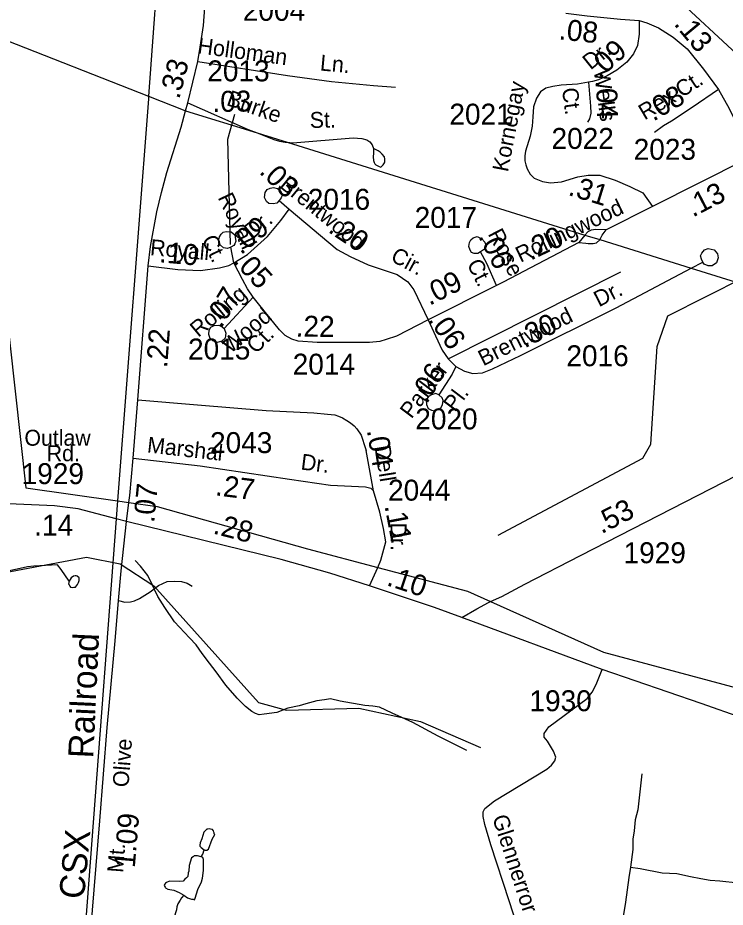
# Model space of a CAD drawing. Extents: x 2206922 to 2357709, y 510027 to 673830.
# Drawn here: x 2287259 to 2291479, y 559014 to 564319 of the extents above; entities that cross this region are included whole.
import ezdxf

# ---------------------------------------------------------------- set-up
doc = ezdxf.new("R2010")
doc.units = 0
for name, color, linetype in [('Exist Boundary Political Urban Extension UEB', 7, 'Continuous'), ('Exist Hydrographic Creek Single Shore', 7, 'Continuous'), ('Exist Hydrographic Misc Water Feature', 7, 'Continuous'), ('Exist Railroad Mainline', 7, 'Continuous'), ('Exist Railroad Mainline Label', 7, 'Continuous'), ('Exist Road Non-System Type 51', 7, 'Continuous'), ('Exist Road Non-System Type 51 Label', 7, 'Continuous'), ('Exist Road Secondary Mileage Hundredths English Label', 7, 'Continuous'), ('Exist Road Secondary Type 51 Attributed', 7, 'Continuous'), ('Exist Road Secondary Type 51 Label', 7, 'Continuous'), ('Exist Road Secondary Type 51 Number Label', 7, 'Continuous'), ('Exist Utilities Electrical Transmission Line', 7, 'Continuous')]:
    doc.layers.add(name, color=color, linetype=linetype)

msp = doc.modelspace()

# ---------------------------------------------------------------- linework, layer by layer
at = {"layer": 'Exist Boundary Political Urban Extension UEB'}
msp.add_line((2287853.8, 561437.5), (2287921.7, 561427.8), dxfattribs=at)
for points in [[(2286979.2, 564267.7), (2287082, 563533.1), (2287306.2, 561515.7), (2287853.8, 561437.5)], [(2287921.7, 561427.8), (2288090.9, 561403.6), (2288987.7, 561151.5), (2289405.5, 561040.9)], [(2289405.5, 561040.9), (2289940.5, 560899.3), (2290079.5, 560836.9)], [(2290079.5, 560836.9), (2290753.2, 560535), (2291902.2, 560226.8), (2292770.9, 559694.4), (2293331.4, 559386.2), (2293609.2, 559370.1)]]:
    msp.add_lwpolyline(points, dxfattribs=at)
at = {"layer": 'Exist Hydrographic Creek Single Shore'}
for points in [[(2291546.8, 564103.5), (2291193.9, 564432), (2290915.9, 564798.4), (2290897.9, 564972.5), (2291069.9, 565297), (2291117.9, 565456.7), (2291099, 565689.9), (2290904, 566130.1), (2290713.9, 566760.3), (2290342, 567423.7), (2290123, 567697), (2289853.9, 567876.3), (2289016.9, 568368.7), (2288882.8, 568427.2), (2288622, 568688.3), (2288246.9, 568777.9), (2288070.8, 568876.5), (2287919.9, 569033.7), (2287807.9, 569373.8)], [(2290125, 561233.1), (2290986.8, 561691.3), (2291035.9, 561775.5), (2291071.9, 562358.5), (2291136.9, 562540.9), (2291593, 562771.1)]]:
    msp.add_lwpolyline(points, dxfattribs=at)
at = {"layer": 'Exist Hydrographic Misc Water Feature'}
for points in [[(2284539.8, 559099.4), (2285578.8, 560206.6), (2285841.9, 560611.3), (2286030.9, 560820.6), (2286146.8, 560903.5), (2286697, 560918.6), (2287668.9, 561102.3), (2287869.9, 561062.2), (2288070.8, 560930.3), (2288694, 560235.6), (2288860.9, 560189.6), (2289293.9, 560200.5), (2289661, 560120.9), (2290019.8, 559966.1)], [(2287496.5, 561055.4), (2287354.6, 561048), (2287316.4, 561043.6), (2287254.9, 561031), (2287159.1, 561010.1), (2287087.6, 560991.3), (2286933.4, 560963.9), (2286831.9, 560941), (2286756, 560922.4), (2286716.4, 560916.2), (2286692.2, 560909.7), (2286656.1, 560907.5), (2286632.6, 560905.4), (2286604.5, 560903.1), (2286584.4, 560904.9), (2286562.4, 560908.6), (2286540.3, 560908.3), (2286534.5, 560909.4), (2286530.4, 560910.2)], [(2287565.3, 560957.9), (2287517, 561027.6), (2287496.5, 561055.4)], [(2289937.8, 559948.8), (2289767, 560033.4), (2289616.1, 560115.7), (2289550, 560145.1), (2289491.8, 560170.6), (2289417.4, 560206.1), (2289377.4, 560213.3), (2289329.4, 560216.9), (2289181.4, 560243.7), (2289123.3, 560257.2), (2289089.1, 560250.7), (2289043.4, 560244.2), (2288977.3, 560227.8), (2288937.4, 560215.5), (2288869.9, 560200.5), (2288804.1, 560176), (2288728, 560165.5), (2288698.5, 560161.1), (2288676.3, 560168.9), (2288654, 560180.8), (2288617.9, 560210.5), (2288567.4, 560259.9), (2288498.9, 560339.2), (2288441.9, 560418.7), (2288401.8, 560470.1), (2288359.1, 560527.7), (2288322.6, 560579.4), (2288282.2, 560620.8), (2288193.6, 560716), (2288136.8, 560801.2), (2288094.2, 560866.9), (2288071.6, 560912.8), (2288063.6, 560930.7), (2288034.7, 560992.6), (2287990.4, 561047.9), (2287959.9, 561081.7)], [(2287565.3, 560957.9), (2287561.7, 560941.8), (2287565.3, 560936), (2287569.7, 560928), (2287573.8, 560922.1), (2287583.6, 560920.2), (2287593.9, 560922.3), (2287603.5, 560922.5), (2287609.6, 560930.5), (2287615.6, 560938.5), (2287621.5, 560950.6), (2287625.6, 560962.6), (2287625.6, 560970.7), (2287625.2, 560978.5), (2287613.3, 560988.4), (2287607.2, 560990.5), (2287601.2, 560990.2), (2287591.2, 560988.1), (2287577, 560978), (2287565.3, 560957.9)], [(2290982.1, 559809), (2290956.7, 559594.7), (2290940.7, 559534.6), (2290935.2, 559468.6), (2290928.2, 559420.5), (2290926.8, 559358.7), (2290913.6, 559252.4)], [(2288370.2, 559356.5), (2288374.1, 559354.7), (2288386, 559354.5), (2288396, 559360.7), (2288419.2, 559418.8), (2288433.3, 559446.8), (2288431.1, 559451.1), (2288429.4, 559457.1), (2288429.2, 559461.1), (2288427.2, 559468.8), (2288420.8, 559477), (2288408.9, 559478.8), (2288401.1, 559480.8), (2288393.1, 559478.8), (2288387.2, 559478.5), (2288379, 559470.4), (2288369.2, 559460.5), (2288357.5, 559422.5), (2288345.8, 559398.3), (2288343.9, 559384.4), (2288344.1, 559378.3), (2288352.1, 559370.2), (2288370.2, 559356.5)], [(2288352.1, 559314.2), (2288362.4, 559330.5), (2288370.2, 559356.5)], [(2288352.1, 559314.2), (2288330.6, 559319.9), (2288310.1, 559320.1), (2288304.4, 559313.7), (2288294.5, 559307.9), (2288281, 559261.7), (2288279.3, 559229.5), (2288275.6, 559219.5), (2288273.6, 559197.5), (2288265.6, 559189.8), (2288255.8, 559181.5), (2288246.1, 559169.6), (2288225.6, 559167.4), (2288163.9, 559168.6), (2288145.9, 559160.4), (2288140.1, 559156.4), (2288134.2, 559148.4), (2288132.1, 559144.2), (2288138.7, 559132.3), (2288140.1, 559128.4), (2288154.5, 559120.5), (2288190.1, 559115.2), (2288220.7, 559101.3), (2288248.6, 559085.3)], [(2288248.6, 559085.3), (2288271.1, 559069.7), (2288282.8, 559065.9), (2288294.9, 559062.1), (2288305, 559062.2), (2288313, 559058.2), (2288316.7, 559068.1), (2288332.7, 559120.1), (2288354, 559164.3), (2288359.7, 559186.6), (2288366.9, 559232.5), (2288366.5, 559298.7), (2288362.6, 559310.2), (2288358.7, 559312.4), (2288352.1, 559314.2)], [(2290913.6, 559252.4), (2290904.2, 559190.6), (2290883.7, 559044.4), (2290851.5, 558848.1), (2290840.2, 558790.3), (2290830.6, 558728), (2290823, 558661.8), (2290814, 558563.9), (2290793.7, 558405.9), (2290787.7, 558376), (2290793.7, 558367.8), (2290796.1, 558361.8), (2290810.1, 558356.1), (2290833.9, 558346.4), (2290990.9, 558293.9), (2291052.5, 558268.4), (2291151.1, 558239.4), (2291217.1, 558225.7), (2291263.3, 558204.2), (2291407.4, 558163.9), (2291433.9, 558148.1)], [(2290913.6, 559252.4), (2290971.5, 559244.9), (2291101.9, 559218.4), (2291189.8, 559215.3), (2291272.1, 559196), (2291333.8, 559184.7), (2291387.9, 559174.9), (2291446, 559171.4), (2291556.1, 559158.5), (2291586, 559154.8), (2291602.2, 559147.1), (2291610.4, 559135.3), (2291586.8, 559063), (2291579.4, 559022.8), (2291577.6, 558999.1), (2291560.2, 558930.8), (2291556.3, 558912.7), (2291554.8, 558870.8), (2291550.9, 558836.9), (2291537.4, 558786.6), (2291532.1, 558736.7), (2291520.6, 558666.7), (2291514.7, 558644.5)], [(2288248.6, 559085.3), (2288234.8, 559069.5), (2288227.1, 559055.3), (2288213.1, 559033), (2288207.6, 559015.2), (2288205.3, 558998.9), (2288199.8, 558981.1), (2288189.7, 558946.9), (2288176.8, 558888.9), (2288167.2, 558836.8), (2288147.9, 558786.6), (2288124.1, 558728.5), (2288096.8, 558674.2), (2288074.9, 558632.1), (2288049.5, 558593.8), (2288029.6, 558561.9), (2287997.6, 558535.5), (2287977.9, 558527.1), (2287945.9, 558518.9), (2287925.8, 558515.5)]]:
    msp.add_lwpolyline(points, dxfattribs=at)
at = {"layer": 'Exist Railroad Mainline'}
for points in [[(2288952.5, 575417.9), (2288939.4, 575328.9), (2288894.6, 575010.5), (2288861, 574754.3), (2288832.1, 574422.3), (2288797.4, 574086.4), (2288738.9, 573282.2), (2288399.4, 568789.4), (2288395.5, 568735.1), (2288273, 567057.4), (2288112.4, 564856.3), (2288039.1, 563851.4), (2288038, 563836.6), (2287853.8, 561437.5), (2287845.7, 561332.3), (2287845.6, 561330.8)], [(2287845.6, 561330.8), (2287410.2, 555579.3), (2287409.6, 555570.6), (2287265.8, 553727)]]:
    msp.add_lwpolyline(points, dxfattribs=at)
at = {"layer": 'Exist Road Non-System Type 51'}
msp.add_line((2289826, 562284.5), (2290856.2, 562803.6), dxfattribs=at)
for points in [[(2288332.1, 564058.7), (2288866.7, 563974.4), (2289130.9, 563939.4), (2289381.5, 563915.1), (2289512.1, 563906)], [(2288272.8, 563812.5), (2288632.8, 563653), (2288686.5, 563632.2)], [(2288686.5, 563632.2), (2288786.2, 563593.7), (2288819.6, 563583.1), (2288854.5, 563577), (2288866.5, 563576.2)], [(2288866.5, 563576.2), (2288898.6, 563574), (2289260, 563602.8), (2289311.6, 563599), (2289340.5, 563591.4), (2289358.7, 563579.3), (2289372.4, 563561), (2289381.5, 563539.8)], [(2289381.5, 563539.8), (2289380, 563512.4), (2289378.5, 563489.6), (2289380, 563468.3), (2289384.5, 563456.2), (2289387.6, 563448.6), (2289395.2, 563442.5), (2289414.9, 563431.9), (2289424, 563428.8), (2289433.1, 563436.4), (2289439.2, 563442.5), (2289446.8, 563454.7), (2289448.3, 563460.7), (2289448.3, 563475.9), (2289445.3, 563489.6), (2289433.1, 563506.3), (2289421, 563518.5), (2289408.8, 563526.1), (2289381.5, 563539.8)], [(2288804, 563212.9), (2288782.3, 563208.7), (2288756.1, 563210.4), (2288742.2, 563222.3), (2288729.9, 563246.2), (2288733.7, 563276.1), (2288745.4, 563294.2), (2288763.4, 563302.5), (2288783.3, 563306.7), (2288807.3, 563300.8), (2288827.4, 563285), (2288835.7, 563261.2), (2288829.8, 563245.1), (2288818.1, 563229)], [(2288818.1, 563229), (2288804.2, 563212.9), (2288804, 563212.9)], [(2288530.2, 562951.8), (2288510.2, 562943.6), (2288486.3, 562947.3), (2288468, 562963.3), (2288458.1, 562975.1), (2288457.9, 562995.1), (2288461.6, 563013.2), (2288471.5, 563029.2), (2288483.4, 563041.3), (2288501.2, 563043.4), (2288531.4, 563041.8), (2288553.4, 563023.9), (2288555.7, 563008.1), (2288559.8, 562986), (2288553.9, 562969.9), (2288548.1, 562959.9), (2288530.2, 562951.8)], [(2290000.3, 562912.9), (2289981.4, 562912.7), (2289965.3, 562918.7), (2289957.2, 562932.4), (2289949.1, 562954.4), (2289952.8, 562978.5), (2289960.7, 562994.5), (2289974.5, 563006.6), (2289998.5, 563014.9), (2290026.6, 563001.2), (2290044.8, 562981.2), (2290053, 562955.5), (2290043.1, 562939.3), (2290019.4, 562923.2)], [(2290019.4, 562923.2), (2290003.4, 562912.9), (2290000.3, 562912.9)], [(2291345.4, 562862.3), (2291337.3, 562878.3), (2291331.2, 562898.2), (2291338.9, 562914.2), (2291354.7, 562934.3), (2291376.6, 562942.5), (2291412.7, 562934.9), (2291433, 562911.1), (2291437.1, 562887), (2291427.5, 562857.1), (2291401.7, 562838.8), (2291377.7, 562838.7), (2291353.6, 562850.4), (2291345.4, 562862.3)], [(2288490.7, 562465.6), (2288499, 562437.9), (2288495.4, 562407.7), (2288475.4, 562389.6), (2288447.7, 562381.3), (2288421.5, 562393), (2288405.4, 562407), (2288399.1, 562430.9), (2288401, 562454.8), (2288410.7, 562472.8), (2288430.7, 562483), (2288458.6, 562485.5), (2288478.8, 562475.7), (2288490.7, 562465.6)], [(2289769.8, 562069.9), (2289751.8, 562077.7), (2289725.8, 562069.6), (2289707.8, 562059.3), (2289694, 562039.2), (2289696.3, 562013.2), (2289706.6, 561989.4), (2289726.6, 561977.6), (2289746.7, 561973.8), (2289766.7, 561982), (2289782.5, 561992.1), (2289792.4, 562010.1), (2289796.1, 562036.2), (2289789.9, 562052.1), (2289769.8, 562069.9)], [(2287974.3, 562039.5), (2288331.1, 562009.6), (2288740.8, 561977), (2289024.3, 561962.1), (2289105.7, 561954), (2289149.1, 561949.9), (2289172.2, 561943.1), (2289195.2, 561932.3), (2289221, 561917.3), (2289244, 561902.4), (2289265.8, 561886.1), (2289280.7, 561867.1), (2289307.8, 561829.1), (2289315.9, 561804.7), (2289325.4, 561773.4), (2289336.3, 561738.2)], [(2287859.9, 560844.2), (2287897, 560833.9), (2287930.6, 560835.9), (2287954.2, 560841.8), (2287985.8, 560855.6), (2288048.9, 560895.1), (2288098.3, 560932.6), (2288149.6, 560956.3), (2288193, 560958.3), (2288234.4, 560956.3), (2288269.9, 560946.5), (2288299.5, 560928.7)], [(2290303.1, 558702.8), (2290189.8, 559051.5), (2290080.9, 559386.2), (2290045.7, 559507.9), (2290035.3, 559555.7), (2290035, 559581.7), (2290044.8, 559601.9), (2290102.3, 559648.3), (2290414.4, 559837.1), (2290442.1, 559861.3), (2290461.8, 559887.5), (2290467.7, 559909.6), (2290453.4, 559945.5), (2290418.8, 560003.2), (2290398.5, 560029), (2290398.4, 560050.9), (2290426.1, 560089.2), (2290654.3, 560259.3), (2290684, 560295.5), (2290709.5, 560341.7), (2290744.7, 560432)]]:
    msp.add_lwpolyline(points, dxfattribs=at)
at = {"layer": 'Exist Road Secondary Type 51 Attributed'}
for p, q in [((2291642, 563493.9), (2291044.4, 563194.2)), ((2288818.1, 563229), (2288877.3, 563177.3)), ((2288546.8, 562856.6), (2288530.2, 562951.8)), ((2288663.4, 562653), (2288490.7, 562465.6)), ((2289380.9, 561497.1), (2289336.3, 561738.2)), ((2287907.8, 561314.7), (2287845.6, 561330.8))]:
    msp.add_line(p, q, dxfattribs=at)
for points in [[(2288036.7, 562839.6), (2288049.6, 562954.7), (2288087.6, 563161.4), (2288116.4, 563276.9), (2288148.3, 563396.9), (2288233.5, 563666.6), (2288260, 563765), (2288272.8, 563812.5), (2288332.1, 564058.7), (2288347.3, 564143.8), (2288365.7, 564273.4), (2288380.7, 564462.1), (2288388.3, 564591.3)], [(2290528.1, 564346.7), (2290656, 564331.1), (2290854.1, 564310.9), (2290966.1, 564302)], [(2290966.1, 564302), (2290964.7, 564222.1), (2290955.6, 564154.3), (2290931.5, 564103.1), (2290890.9, 564054.9), (2290832.2, 564006.7), (2290775, 563972.1), (2290722.3, 563949.5), (2290686.2, 563939), (2290663.6, 563934.4)], [(2290966.1, 564302), (2291011.3, 564288.4), (2291080.6, 564259.7), (2291169, 564204), (2291252.2, 564133.2), (2291350, 564012.8), (2291438.8, 563891.5)], [(2290663.6, 563934.4), (2290597.4, 563922.4), (2290499.6, 563917.9), (2290449.9, 563909.6), (2290409.3, 563899), (2290376.1, 563878), (2290352.1, 563838.8), (2290335.5, 563787.6), (2290331, 563728.9), (2290326.5, 563673.1), (2290315.9, 563612.9), (2290287.3, 563524), (2290282.8, 563495.4), (2290282.8, 563465.3), (2290288.8, 563442.7), (2290296.4, 563418.6), (2290315.9, 563387), (2290340, 563362.9), (2290388.2, 563341.8), (2290436.3, 563334.3), (2290501.1, 563340.3), (2290600.4, 563370.4), (2290662.1, 563381), (2290729.9, 563379.5), (2290821.7, 563350.9), (2290910.5, 563313.2), (2290987.2, 563275.5), (2291044.4, 563194.2)], [(2290663.6, 563934.4), (2290674.2, 563792.9), (2290677.2, 563750.7), (2290669.6, 563716.1), (2290656.4, 563696.9)], [(2291438.8, 563891.5), (2291280.8, 563783.1), (2291157.3, 563701.8), (2291110.7, 563674.6), (2291056.5, 563634)], [(2291438.8, 563891.5), (2291502, 563777.1), (2291599.8, 563578.3), (2291642, 563493.9)], [(2288546.8, 562856.6), (2288628.6, 562906.7), (2288748.2, 563014.7), (2288828.7, 563109), (2288877.3, 563177.3)], [(2288877.3, 563177.3), (2289164.3, 562937.2), (2289241.8, 562894.7), (2289348.1, 562846.1), (2289431.6, 562817.2), (2289522.7, 562788.3), (2289585, 562744.3), (2289621.5, 562697.2), (2289706.6, 562517.9)], [(2291044.4, 563194.2), (2290769, 563053.7)], [(2290769, 563053.7), (2290707.8, 563056.7), (2290679.7, 563051.7), (2290659.6, 563041.6), (2290641.5, 563023.4), (2290605.4, 562978.4)], [(2290730.7, 562995.6), (2290744.9, 563021.5), (2290769, 563053.7)], [(2290605.4, 562978.4), (2290153.2, 562741.1), (2290114.7, 562721.8)], [(2290605.4, 562978.4), (2290647.6, 562974.3), (2290660.6, 562972.3), (2290691.7, 562972.3), (2290710.8, 562977.4), (2290730.7, 562995.6)], [(2290114.7, 562721.8), (2290057.3, 562853.3), (2290019.4, 562923.2)], [(2288036.7, 562839.6), (2288214.4, 562817.2), (2288348.7, 562811.8), (2288461.5, 562827.3), (2288485.4, 562833.4), (2288517.1, 562841.7), (2288546.8, 562856.6)], [(2288663.4, 562653), (2288628.2, 562701.9), (2288599.7, 562757.5), (2288546.8, 562856.6)], [(2289872.1, 562238.3), (2289923.7, 562211.2), (2289973.9, 562196.3), (2290030.9, 562201.7), (2290090, 562224.8), (2290257.4, 562305.5), (2290828.3, 562589.5), (2291276.2, 562825.8), (2291345.4, 562862.3)], [(2287947.2, 561692), (2287974.3, 562039.5), (2288036.7, 562839.6)], [(2290114.7, 562721.8), (2289706.6, 562517.9)], [(2289706.6, 562517.9), (2289518.1, 562420.9), (2289455.7, 562399.2), (2289417.7, 562388.3), (2289356.6, 562382.9), (2289268.5, 562382.9), (2289044.6, 562382.9), (2288930.7, 562391), (2288894.1, 562401.9), (2288854.7, 562423.6), (2288819.4, 562457.5), (2288759.8, 562530.8), (2288663.4, 562653)], [(2289706.6, 562517.9), (2289751.4, 562422.9), (2289790.7, 562336.1), (2289826, 562284.5), (2289872.1, 562238.3)], [(2289872.1, 562238.3), (2289850.4, 562193.5), (2289769.8, 562069.9)], [(2289908, 560741.5), (2289998, 560793.5), (2290067.3, 560831.3), (2290079.5, 560836.9), (2290146.8, 560868.1), (2290284, 560941.3), (2290616.3, 561112.3), (2291317.9, 561471.5), (2291929.3, 561786.2)], [(2287907.8, 561314.7), (2287921.7, 561427.8), (2287926.8, 561470.1), (2287947.2, 561692)], [(2287947.2, 561692), (2288346, 561647.2), (2288879.1, 561567.8), (2289124.7, 561530.5), (2289333.1, 561522.1), (2289365.3, 561512.5), (2289380.9, 561497.1)], [(2289356.8, 560930.7), (2289405.5, 561040.9), (2289424.5, 561083.9), (2289454.3, 561192.5), (2289440.9, 561272.5), (2289418.4, 561371.1), (2289380.9, 561497.1)], [(2287845.6, 561330.8), (2287618.8, 561389.6), (2287476.8, 561407.4), (2287157.1, 561422.2)], [(2287309.8, 553730.8), (2287424.9, 555288.8), (2287522.6, 556545.7), (2287594.5, 557503.3), (2287640.6, 558169.1), (2287693.5, 558850.4), (2287749.1, 559529.8), (2287791.2, 560086.3), (2287838.7, 560602.1), (2287859.9, 560844.2), (2287875.3, 561020.1), (2287907.8, 561314.7)], [(2289356.8, 560930.7), (2289120.6, 561005.9), (2288828.9, 561088.7), (2287907.8, 561314.7)], [(2289908, 560741.5), (2289743.6, 560802.3), (2289356.8, 560930.7)], [(2293599, 559221.6), (2293496.8, 559232.4), (2293406.1, 559245.3), (2293315.4, 559267.5), (2293218.7, 559299.7), (2293041.4, 559394.5), (2292791.1, 559525.1), (2292504.6, 559688.9), (2292129.1, 559890.9), (2291851.9, 560034.6), (2291737.4, 560081.4), (2291582.9, 560142), (2291334.2, 560229.5), (2290744.7, 560432), (2289908, 560741.5)]]:
    msp.add_lwpolyline(points, dxfattribs=at)
at = {"layer": 'Exist Road Secondary Type 51 Number Label'}
msp.add_lwpolyline([(2288528, 562966.2), (2288511, 563595.1), (2288553.5, 563743.8)], dxfattribs=at)
at = {"layer": 'Exist Utilities Electrical Transmission Line'}
for p, q in [((2286979.2, 564267.7), (2288039.1, 563851.4)), ((2288260, 563765), (2288686.5, 563632.2)), ((2288686.5, 563632.2), (2288866.5, 563576.2)), ((2288866.5, 563576.2), (2290641.5, 563023.4)), ((2290641.5, 563023.4), (2290730.5, 562995.7)), ((2290730.5, 562995.7), (2291276.2, 562825.8)), ((2291276.2, 562825.8), (2292190.6, 562541))]:
    msp.add_line(p, q, dxfattribs=at)
msp.add_lwpolyline([(2288039.1, 563851.4), (2288254.7, 563766.7), (2288260, 563765)], dxfattribs=at)

# ---------------------------------------------------------------- texts
at = {"layer": 'Exist Railroad Mainline Label'}
for s, rotation, p in [('Railroad', 87.337, (2287708.9, 559899.8)), ('CSX', 84.6076, (2287653.4, 559058.3))]:
    msp.add_text(s, height=150, rotation=rotation, dxfattribs=at).set_placement(p)
at = {"layer": 'Exist Road Non-System Type 51 Label'}
for s, rotation, p in [('Holloman', 352.2726, (2288327.8, 564108)), ('Ln.', 354.8366, (2289059, 564004.9)), ('Burke', 340.6286, (2288498.1, 563799.9)), ('St.', 1.0956, (2289001.4, 563661.7)), ('Glennerror', 288.0003, (2290088, 559548.8))]:
    msp.add_text(s, height=95, rotation=rotation, dxfattribs=at).set_placement(p)
at = {"layer": 'Exist Road Secondary Mileage Hundredths English Label'}
for s, rotation, p in [('.08', 354.1777, (2290482.8, 564190.6)), ('.13', 309.7861, (2291168.4, 564280.7)), ('.09', 42.5596, (2290730.5, 563951.6)), ('.33', 75.3341, (2288221.6, 563829.7)), ('.04', 271.8198, (2290707.9, 563944.9)), ('.08', 30.8929, (2291049.8, 563698.5)), ('.03', 0.7733, (2288420.7, 563757.1)), ('.03', 316.2853, (2288693.1, 563395.7)), ('.31', 342.8574, (2290536.2, 563263.2)), ('.13', 27.4138, (2291285.2, 563127.1)), ('.09', 39.723, (2288589.8, 562901.6)), ('.20', 325.996, (2289104.2, 563044.7)), ('.20', 25.5907, (2290317.4, 562869.2)), ('.06', 296.6798, (2290003.9, 563015.1)), ('.10', 354.8902, (2288099.2, 562861.3)), ('.05', 312.7103, (2288539.6, 562862.9)), ('.09', 26.776, (2289714.6, 562600.5)), ('.07', 59.0138, (2288472.9, 562463.6)), ('.22', 359.276, (2288915.9, 562417.7)), ('.06', 305.8341, (2289701.8, 562516.5)), ('.30', 27.183, (2290281.9, 562346.3)), ('.22', 85.765, (2288149.6, 562228.3)), ('.06', 59.0138, (2289698.4, 562011.7)), ('.04', 279.1651, (2289340.7, 561858.5)), ('.27', 352.8522, (2288433.2, 561471)), ('.07', 84.4733, (2288072.3, 561303.8)), ('.53', 27.3789, (2290740.7, 561238.3)), ('.11', 280.7088, (2289446.2, 561407.3)), ('.14', 0.0444, (2287356.9, 561229.6)), ('.28', 345.5405, (2288418.4, 561243.7)), ('.10', 341.6358, (2289453.6, 560935.5)), ('1.09', 85.2541, (2287956.7, 559245.5))]:
    msp.add_text(s, height=125, rotation=rotation, dxfattribs=at).set_placement(p)
at = {"layer": 'Exist Road Secondary Type 51 Label'}
for s, rotation, p in [('Dr.', 38.5525, (2290675.4, 564004.5)), ('Wells', 277.5915, (2290694.1, 564003.6)), ('Ct.', 33.3841, (2291220.7, 563839.8)), ('Kornegay', 79.0344, (2290182.1, 563395.5)), ('Ct.', 277.5915, (2290504.4, 563896.4)), ('Rex', 30.8929, (2290997.7, 563706.4)), ('Brentwood', 320.837, (2288814.4, 563312.1)), ('Royall', 295.4012, (2288450, 563247.6)), ('Rollingwood', 25.5907, (2290257.1, 562857.1)), ('Dr.', 39.723, (2288657.4, 562994.6)), ('Rose', 297.0489, (2290060.8, 563030.9)), ('Ct.', 295.4012, (2288353.3, 562996.7)), ('Royall', 354.8902, (2288045.5, 562904)), ('Cir.', 331.6101, (2289476.6, 562872.6)), ('Ct.', 297.0489, (2289935.2, 562851)), ('Rolling', 39.833, (2288335.4, 562409.1)), ('Dr.', 27.183, (2290725.4, 562592)), ('Wood', 39.833, (2288527.4, 562312.5)), ('Brentwood', 26.5452, (2290035.3, 562239.6)), ('Ct.', 44.3029, (2288678.9, 562310.2)), ('Parker', 53.0113, (2289606.6, 561923)), ('Pl.', 53.0113, (2289865.3, 561963.1)), ('Marshal', 353.6445, (2288027, 561726.3)), ('Dell', 279.1651, (2289386.2, 561762.1)), ('Dr.', 352.8522, (2288943.5, 561625.1)), ('Dr.', 270.4914, (2289482.5, 561308)), ('Olive', 85.6696, (2287918.8, 559727.1)), ('Mt.', 85.6696, (2287886.9, 559217))]:
    msp.add_text(s, height=95, rotation=rotation, dxfattribs=at).set_placement(p)
for s, p in [('Outlaw', (2287298.4, 561766.4)), ('Rd.', (2287431.4, 561674.3))]:
    msp.add_text(s, height=95, dxfattribs=at).set_placement(p)
at = {"layer": 'Exist Road Secondary Type 51 Number Label'}
for s, p in [('2004', (2288600.9, 564301.1)), ('2013', (2288389.2, 563940)), ('2021', (2289833.3, 563681.7)), ('2022', (2290442.5, 563537)), ('2023', (2290932.7, 563472)), ('2016', (2288988.8, 563173.8)), ('2017', (2289626.3, 563065.9)), ('2015', (2288274.3, 562280.7)), ('2014', (2288898.6, 562190.3)), ('2016', (2290531.2, 562240.6)), ('2020', (2289629.9, 561863.9)), ('2043', (2288405.6, 561722.5)), ('1929', (2287281.7, 561537.5)), ('2044', (2289467.4, 561438.8)), ('1929', (2290872.3, 561065.6)), ('1930', (2290310.9, 560182.8))]:
    msp.add_text(s, height=125, dxfattribs=at).set_placement(p)

doc.saveas('drawing.dxf')
